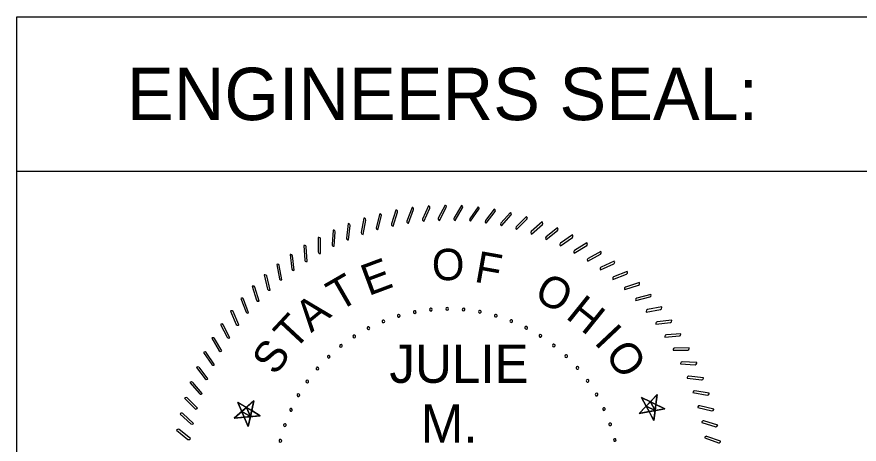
# Model space of a CAD drawing. Extents: x 0 to 34, y 0 to 22.
# Drawn here: x 9.25 to 11.982, y 5.614 to 7 of the extents above; entities that cross this region are included whole.
import ezdxf

# ---------------------------------------------------------------- set-up
doc = ezdxf.new("R2010")
doc.units = 0
doc.layers.add('Default', color=7, linetype='Continuous')
doc.layers.add('SH_Data', color=7, linetype='Continuous')

msp = doc.modelspace()

# ---------------------------------------------------------------- linework, layer by layer
at = {"layer": 'Default'}
for p, q in [((11.3269, 5.7755), (11.2684, 5.7141)), ((11.3519, 5.7294), (11.2753, 5.7661)), ((11.2753, 5.7661), (11.3157, 5.6914)), ((11.3157, 5.6914), (11.3269, 5.7755)), ((10.0187, 5.7548), (9.9551, 5.6985)), ((10.0396, 5.7067), (9.9665, 5.7497)), ((9.9665, 5.7497), (10.0003, 5.6719)), ((10.0003, 5.6719), (10.0187, 5.7548)), ((11.2907, 5.7375), (11.32, 5.7235)), ((11.32, 5.7235), (11.3046, 5.752)), ((9.9794, 5.72), (10.0073, 5.7036)), ((10.0073, 5.7036), (9.9944, 5.7333)), ((11.2684, 5.7141), (11.3519, 5.7294)), ((9.9551, 5.6985), (10.0396, 5.7067))]:
    msp.add_line(p, q, dxfattribs=at)
for points in [[(10.481, 6.373), (10.4791, 6.3736), (10.465, 6.3285)], [(10.4702, 6.3215), (10.4844, 6.3666)], [(10.5338, 6.3814), (10.532, 6.3821), (10.5152, 6.3379)], [(10.52, 6.3306), (10.5368, 6.3748)], [(10.587, 6.3866), (10.5852, 6.3874), (10.5658, 6.3443)], [(10.5702, 6.3367), (10.5896, 6.3798)], [(10.6404, 6.3886), (10.6387, 6.3895), (10.6168, 6.3476)], [(10.6206, 6.3399), (10.6426, 6.3817)], [(10.6939, 6.3874), (10.6922, 6.3884), (10.6678, 6.3479)], [(10.6712, 6.3399), (10.6956, 6.3804)], [(10.7472, 6.383), (10.7456, 6.3841), (10.7188, 6.3452)], [(10.7217, 6.337), (10.7485, 6.3759)], [(10.8001, 6.3754), (10.7985, 6.3766), (10.7695, 6.3394)], [(10.7719, 6.331), (10.801, 6.3683)], [(10.8525, 6.3647), (10.851, 6.366), (10.8197, 6.3305)], [(10.3774, 6.3469), (10.3754, 6.3472), (10.3668, 6.3008)], [(10.3728, 6.2945), (10.3815, 6.3409)], [(10.4288, 6.3615), (10.4269, 6.362), (10.4155, 6.3161)], [(10.4211, 6.3095), (10.4325, 6.3553)], [(10.5684, 6.3376), (10.5702, 6.3367)], [(10.6189, 6.3408), (10.6206, 6.3399)], [(10.6695, 6.3409), (10.6712, 6.3399)], [(10.7201, 6.3381), (10.7217, 6.337)], [(10.8217, 6.3221), (10.8529, 6.3575)], [(10.9041, 6.3509), (10.9027, 6.3523), (10.8694, 6.3187)], [(10.8708, 6.3102), (10.9041, 6.3437)], [(10.3269, 6.3292), (10.325, 6.3294), (10.3191, 6.2825)], [(10.3255, 6.2766), (10.3313, 6.3235)], [(10.4684, 6.3221), (10.4702, 6.3215)], [(10.5181, 6.3313), (10.52, 6.3306)], [(10.7704, 6.3322), (10.7719, 6.331)], [(10.8202, 6.3234), (10.8217, 6.3221)], [(10.8694, 6.3115), (10.8708, 6.3102)], [(10.9548, 6.334), (10.9535, 6.3354), (10.9183, 6.304)], [(10.9192, 6.2953), (10.9544, 6.3268)], [(11.0045, 6.3141), (11.0032, 6.3156), (10.9662, 6.2863)], [(10.2296, 6.285), (10.2277, 6.285), (10.2275, 6.2377)], [(10.2776, 6.3086), (10.2756, 6.3087), (10.2726, 6.2615)], [(10.2793, 6.256), (10.2824, 6.3032)], [(10.3709, 6.2948), (10.3728, 6.2945)], [(10.4192, 6.3099), (10.4211, 6.3095)], [(10.9179, 6.2968), (10.9192, 6.2953)], [(10.9666, 6.2776), (11.0036, 6.3069)], [(11.0128, 6.2571), (11.0515, 6.2842)], [(11.0528, 6.2913), (11.0517, 6.2929), (11.0129, 6.2658)], [(10.1831, 6.2586), (10.1812, 6.2585), (10.1838, 6.2113)], [(10.2345, 6.2326), (10.2347, 6.2799)], [(10.2774, 6.2561), (10.2793, 6.256)], [(10.3235, 6.2769), (10.3255, 6.2766)], [(10.9653, 6.2792), (10.9666, 6.2776)], [(11.0117, 6.2587), (11.0128, 6.2571)], [(11.0577, 6.2339), (11.098, 6.2586)], [(11.0997, 6.2656), (11.0987, 6.2673), (11.0583, 6.2426)], [(10.1383, 6.2295), (10.1363, 6.2293), (10.1418, 6.1823)], [(10.1911, 6.2066), (10.1885, 6.2538)], [(10.2325, 6.2326), (10.2345, 6.2326)], [(11.0567, 6.2356), (11.0577, 6.2339)], [(11.1012, 6.208), (11.1429, 6.2303)], [(11.145, 6.2371), (11.144, 6.2389), (11.1023, 6.2167)], [(10.1494, 6.1781), (10.1439, 6.225)], [(10.1892, 6.2065), (10.1911, 6.2066)], [(11.1002, 6.2098), (11.1012, 6.208)], [(11.1884, 6.206), (11.1876, 6.2078), (11.1447, 6.1881)], [(10.0953, 6.1977), (10.0933, 6.1974), (10.1016, 6.1509)], [(10.1094, 6.1471), (10.1012, 6.1936)], [(10.1474, 6.1779), (10.1494, 6.1781)], [(11.1422, 6.1814), (11.143, 6.1796)], [(11.143, 6.1796), (11.186, 6.1993)], [(11.23, 6.1724), (11.2293, 6.1742), (11.1852, 6.1572)], [(10.0542, 6.1635), (10.0523, 6.163), (10.0633, 6.117)], [(10.0714, 6.1138), (10.0604, 6.1597)], [(10.1075, 6.1467), (10.1094, 6.1471)], [(11.1823, 6.1506), (11.183, 6.1487)], [(11.183, 6.1487), (11.2271, 6.1658)], [(10.0153, 6.1268), (10.0135, 6.1262), (10.0272, 6.081)], [(10.0354, 6.0782), (10.0217, 6.1234)], [(11.2212, 6.1155), (11.2662, 6.1299)], [(11.2695, 6.1363), (11.2689, 6.1382), (11.2239, 6.1238)], [(10.0695, 6.1133), (10.0714, 6.1138)], [(11.2206, 6.1174), (11.2212, 6.1155)], [(11.2572, 6.0801), (11.303, 6.0918)], [(11.3067, 6.098), (11.3062, 6.0999), (11.2604, 6.0882)], [(9.9787, 6.0879), (9.9768, 6.0872), (9.9933, 6.0429)], [(10.0016, 6.0406), (9.9852, 6.0849)], [(10.0335, 6.0776), (10.0354, 6.0782)], [(11.2568, 6.082), (11.2572, 6.0801)], [(9.9444, 6.0468), (9.9426, 6.0461), (9.9617, 6.0028)], [(9.9702, 6.001), (9.9511, 6.0442)], [(9.9998, 6.0399), (10.0016, 6.0406)], [(11.2908, 6.0445), (11.2911, 6.0426)], [(11.2911, 6.0426), (11.3376, 6.0515)], [(11.3416, 6.0575), (11.3412, 6.0594), (11.2948, 6.0505)], [(11.374, 6.0149), (11.3737, 6.0169), (11.3269, 6.0107)], [(9.9127, 6.0038), (9.9109, 6.0029), (9.9325, 5.9609)], [(9.9411, 5.9596), (9.9195, 6.0016)], [(9.9684, 6.0002), (9.9702, 6.001)], [(11.3225, 6.005), (11.3227, 6.0031)], [(11.3227, 6.0031), (11.3696, 6.0092)], [(9.8836, 5.959), (9.8819, 5.958), (9.906, 5.9173)], [(9.9146, 5.9165), (9.8905, 5.9572)], [(9.9394, 5.9587), (9.9411, 5.9596)], [(11.3518, 5.9637), (11.3519, 5.9618)], [(11.3519, 5.9618), (11.3991, 5.9651)], [(11.4038, 5.9705), (11.4036, 5.9725), (11.3565, 5.9692)], [(9.8572, 5.9125), (9.8556, 5.9114), (9.882, 5.8722)], [(9.8907, 5.872), (9.8643, 5.9111)], [(9.9129, 5.9155), (9.9146, 5.9165)], [(11.3785, 5.9208), (11.3786, 5.9188)], [(11.3786, 5.9188), (11.4258, 5.9193)], [(11.4308, 5.9244), (11.4308, 5.9264), (11.3836, 5.9259)], [(11.4027, 5.8763), (11.4026, 5.8743)], [(11.4026, 5.8743), (11.4498, 5.872)], [(11.4551, 5.8768), (11.4552, 5.8788), (11.408, 5.8811)], [(9.8336, 5.8645), (9.8321, 5.8633), (9.8608, 5.8258)], [(9.8695, 5.826), (9.8408, 5.8636)], [(9.8891, 5.8709), (9.8907, 5.872)], [(9.868, 5.8248), (9.8695, 5.826)], [(11.4241, 5.8304), (11.4239, 5.8285)], [(11.4239, 5.8285), (11.4709, 5.8233)], [(11.4765, 5.8278), (11.4767, 5.8298), (11.4297, 5.8349)], [(9.813, 5.8152), (9.8115, 5.8139), (9.8425, 5.7782)], [(9.8511, 5.7789), (9.8202, 5.8147)], [(9.7954, 5.7647), (9.794, 5.7633), (9.827, 5.7295)], [(9.8356, 5.7308), (9.8025, 5.7646)], [(9.8496, 5.7777), (9.8511, 5.7789)], [(11.4428, 5.7833), (11.4425, 5.7814)], [(11.4425, 5.7814), (11.4891, 5.7735)], [(11.4949, 5.7776), (11.4952, 5.7796), (11.4487, 5.7875)], [(11.5103, 5.7264), (11.5107, 5.7283), (11.4647, 5.7391)], [(9.7808, 5.7133), (9.7794, 5.7118), (9.8144, 5.68)], [(9.8229, 5.6819), (9.7879, 5.7136)], [(9.8342, 5.7294), (9.8356, 5.7308)], [(11.4586, 5.7353), (11.4582, 5.7333)], [(11.4582, 5.7333), (11.5042, 5.7226)], [(9.8216, 5.6804), (9.8229, 5.6819)], [(11.4715, 5.6863), (11.471, 5.6844)], [(11.471, 5.6844), (11.5163, 5.671)], [(11.5226, 5.6744), (11.5232, 5.6763), (11.4778, 5.6897)], [(9.7693, 5.6611), (9.768, 5.6595), (9.8049, 5.6299)], [(9.8132, 5.6322), (9.7764, 5.6619)], [(9.812, 5.6307), (9.8132, 5.6322)], [(11.4815, 5.6367), (11.4808, 5.6348)], [(11.4808, 5.6348), (11.5252, 5.6187)], [(11.5318, 5.6217), (11.5324, 5.6236), (11.488, 5.6397)]]:
    msp.add_lwpolyline(points, dxfattribs=at)
for points in [[(11.2753, 5.7661), (11.3046, 5.752), (11.2753, 5.7661), (11.2907, 5.7375)], [(11.2907, 5.7375), (11.2753, 5.7661), (11.3046, 5.752), (11.3046, 5.752)], [(11.3269, 5.7755), (11.3046, 5.752), (11.3269, 5.7755), (11.3226, 5.7434)], [(11.3226, 5.7434), (11.3269, 5.7755), (11.3046, 5.752), (11.3046, 5.752)], [(9.9794, 5.72), (9.9665, 5.7497), (9.9944, 5.7333), (9.9944, 5.7333)], [(9.9665, 5.7497), (9.9944, 5.7333), (9.9665, 5.7497), (9.9794, 5.72)], [(10.0117, 5.7231), (10.0187, 5.7548), (9.9944, 5.7333), (9.9944, 5.7333)], [(10.0187, 5.7548), (9.9944, 5.7333), (10.0187, 5.7548), (10.0117, 5.7231)], [(11.2684, 5.7141), (11.2907, 5.7375), (11.2684, 5.7141), (11.3003, 5.7199)], [(11.3003, 5.7199), (11.2684, 5.7141), (11.2907, 5.7375), (11.2907, 5.7375)], [(11.2907, 5.7375), (11.32, 5.7235), (11.2907, 5.7375), (11.3046, 5.752)], [(11.3046, 5.752), (11.2907, 5.7375), (11.32, 5.7235), (11.32, 5.7235)], [(11.2907, 5.7375), (11.32, 5.7235), (11.2907, 5.7375), (11.3003, 5.7199)], [(11.3003, 5.7199), (11.2907, 5.7375), (11.32, 5.7235), (11.32, 5.7235)], [(11.32, 5.7235), (11.3226, 5.7434), (11.32, 5.7235), (11.3046, 5.752)], [(11.3046, 5.752), (11.32, 5.7235), (11.3226, 5.7434), (11.3226, 5.7434)], [(11.3226, 5.7434), (11.3519, 5.7294), (11.3226, 5.7434), (11.32, 5.7235)], [(11.32, 5.7235), (11.3226, 5.7434), (11.3519, 5.7294), (11.3519, 5.7294)], [(9.9874, 5.7016), (9.9551, 5.6985), (9.9794, 5.72), (9.9794, 5.72)], [(9.9551, 5.6985), (9.9794, 5.72), (9.9551, 5.6985), (9.9874, 5.7016)], [(9.9944, 5.7333), (9.9794, 5.72), (10.0073, 5.7036), (10.0073, 5.7036)], [(9.9794, 5.72), (10.0073, 5.7036), (9.9794, 5.72), (9.9944, 5.7333)], [(9.9874, 5.7016), (9.9794, 5.72), (10.0073, 5.7036), (10.0073, 5.7036)], [(9.9794, 5.72), (10.0073, 5.7036), (9.9794, 5.72), (9.9874, 5.7016)], [(9.9944, 5.7333), (10.0073, 5.7036), (10.0117, 5.7231), (10.0117, 5.7231)], [(10.0073, 5.7036), (10.0117, 5.7231), (10.0073, 5.7036), (9.9944, 5.7333)], [(10.0073, 5.7036), (10.0117, 5.7231), (10.0396, 5.7067), (10.0396, 5.7067)], [(10.0117, 5.7231), (10.0396, 5.7067), (10.0117, 5.7231), (10.0073, 5.7036)], [(11.32, 5.7235), (11.3157, 5.6914), (11.32, 5.7235), (11.3003, 5.7199)], [(11.3003, 5.7199), (11.32, 5.7235), (11.3157, 5.6914), (11.3157, 5.6914)], [(9.9874, 5.7016), (10.0073, 5.7036), (10.0003, 5.6719), (10.0003, 5.6719)], [(10.0073, 5.7036), (10.0003, 5.6719), (10.0073, 5.7036), (9.9874, 5.7016)]]:
    msp.add_lwpolyline(points, close=True, dxfattribs=at)
for centre, radius, start, end in [((10.4795, 6.3681), 0.00508, 342.6706, 72.6706), ((10.532, 6.3766), 0.00508, 339.242, 69.242), ((10.5849, 6.3819), 0.00508, 335.8134, 65.8134), ((10.6381, 6.3841), 0.00508, 332.3849, 62.3849), ((10.6913, 6.383), 0.00508, 328.9563, 58.9563), ((10.7443, 6.3788), 0.00508, 325.5277, 55.5277), ((10.797, 6.3714), 0.00508, 322.0992, 52.0992), ((10.8491, 6.3609), 0.00508, 318.6706, 48.6706), ((10.3765, 6.3419), 0.00508, 349.5277, 79.5277), ((10.4276, 6.3566), 0.00508, 346.0992, 76.0992), ((10.5199, 6.3361), 0.00508, 159.242, 249.242), ((10.5705, 6.3422), 0.00508, 155.8134, 245.8134), ((10.6213, 6.3453), 0.00508, 152.3849, 242.3849), ((10.6722, 6.3453), 0.00508, 148.9563, 238.9563), ((10.723, 6.3423), 0.00508, 145.5277, 235.5277), ((10.7735, 6.3362), 0.00508, 142.0992, 232.0992), ((10.9005, 6.3473), 0.00508, 315.242, 45.242), ((10.3263, 6.3242), 0.00508, 352.9563, 82.9563), ((10.4204, 6.3149), 0.00508, 166.0992, 256.0992), ((10.4699, 6.327), 0.00508, 162.6706, 252.6706), ((10.8236, 6.3272), 0.00508, 138.6706, 228.6706), ((10.873, 6.3152), 0.00508, 135.242, 225.242), ((10.951, 6.3306), 0.00508, 311.8134, 41.8134), ((11.0005, 6.3109), 0.00508, 308.3849, 38.3849), ((10.2296, 6.2799), 0.00508, 359.8134, 89.8134), ((10.2773, 6.3035), 0.00508, 356.3849, 86.3849), ((10.3718, 6.2998), 0.00508, 169.5277, 259.5277), ((10.9217, 6.3002), 0.00508, 131.8134, 221.8134), ((10.9693, 6.2823), 0.00508, 128.3849, 218.3849), ((11.0486, 6.2883), 0.00508, 304.9563, 34.9563), ((10.1834, 6.2535), 0.00508, 3.242, 93.242), ((10.2777, 6.2612), 0.00508, 176.3849, 266.3849), ((10.3242, 6.2819), 0.00508, 172.9563, 262.9563), ((11.0158, 6.2617), 0.00508, 124.9563, 214.9563), ((11.0954, 6.2629), 0.00508, 301.5277, 31.5277), ((10.1389, 6.2244), 0.00508, 6.6706, 96.6706), ((10.2325, 6.2377), 0.00508, 179.8134, 269.8134), ((11.061, 6.2382), 0.00508, 121.5277, 211.5277), ((11.1405, 6.2347), 0.00508, 298.0992, 28.0992), ((10.1889, 6.2116), 0.00508, 183.242, 273.242), ((11.1047, 6.2122), 0.00508, 118.0992, 208.0992), ((11.1838, 6.2039), 0.00508, 294.6706, 24.6706), ((10.0962, 6.1927), 0.00508, 10.0992, 100.0992), ((10.1468, 6.1829), 0.00508, 186.6706, 276.6706), ((11.1468, 6.1835), 0.00508, 114.6706, 204.6706), ((10.0554, 6.1585), 0.00508, 13.5277, 103.5277), ((10.1066, 6.1517), 0.00508, 190.0992, 280.0992), ((11.1871, 6.1524), 0.00508, 111.242, 201.242), ((11.2253, 6.1706), 0.00508, 291.242, 21.242), ((10.0168, 6.1219), 0.00508, 16.9563, 106.9563), ((11.2254, 6.119), 0.00508, 107.8134, 197.8134), ((11.2646, 6.1348), 0.00508, 287.8134, 17.8134), ((10.0683, 6.1182), 0.00508, 193.5277, 283.5277), ((11.3018, 6.0967), 0.00508, 284.3849, 14.3849), ((9.9805, 6.0831), 0.00508, 20.3849, 110.3849), ((10.0321, 6.0825), 0.00508, 196.9563, 286.9563), ((11.2617, 6.0833), 0.00508, 104.3849, 194.3849), ((9.9465, 6.0422), 0.00508, 23.8134, 113.8134), ((9.998, 6.0447), 0.00508, 200.3849, 290.3849), ((10.5403, 6.0428), 0.00437, 10.9091, 190.9091), ((10.5403, 6.0428), 0.00437, 190.9091, 10.9091), ((10.5929, 6.0505), 0.00437, 5.4545, 185.4545), ((10.5929, 6.0505), 0.00437, 185.4545, 5.4545), ((10.6459, 6.0531), 0.00437, 0, 180), ((10.6459, 6.0531), 0.00437, 180, 0), ((10.699, 6.0507), 0.00437, 354.5455, 174.5455), ((10.699, 6.0507), 0.00437, 174.5455, 354.5455), ((10.7516, 6.0433), 0.00437, 169.0909, 349.0909), ((10.7516, 6.0433), 0.00437, 349.0909, 169.0909), ((11.2958, 6.0455), 0.00508, 100.9563, 190.9563), ((11.3366, 6.0565), 0.00508, 280.9563, 10.9563), ((10.4386, 6.0127), 0.00437, 21.8182, 201.8182), ((10.4386, 6.0127), 0.00437, 201.8182, 21.8182), ((10.4887, 6.0302), 0.00437, 16.3636, 196.3636), ((10.4887, 6.0302), 0.00437, 196.3636, 16.3636), ((10.8032, 6.0309), 0.00437, 163.6364, 343.6364), ((10.8032, 6.0309), 0.00437, 343.6364, 163.6364), ((10.8534, 6.0137), 0.00437, 158.1818, 338.1818), ((10.8534, 6.0137), 0.00437, 338.1818, 158.1818), ((11.3275, 6.0057), 0.00508, 97.5277, 187.5277), ((11.3689, 6.0143), 0.00508, 277.5277, 7.5277), ((9.915, 5.9993), 0.00508, 27.242, 117.242), ((9.9663, 6.0048), 0.00508, 203.8134, 293.8134), ((10.3903, 5.9905), 0.00437, 27.2727, 207.2727), ((10.3903, 5.9905), 0.00437, 207.2727, 27.2727), ((10.9018, 5.9917), 0.00437, 152.7273, 332.7273), ((10.9018, 5.9917), 0.00437, 332.7273, 152.7273), ((9.8862, 5.9546), 0.00508, 30.6706, 120.6706), ((9.937, 5.9632), 0.00508, 207.242, 297.242), ((10.3444, 5.9638), 0.00437, 32.7273, 212.7273), ((10.3444, 5.9638), 0.00437, 212.7273, 32.7273), ((10.9479, 5.9653), 0.00437, 147.2727, 327.2727), ((10.9479, 5.9653), 0.00437, 327.2727, 147.2727), ((11.3568, 5.9641), 0.00508, 94.0992, 184.0992), ((11.3987, 5.9702), 0.00508, 274.0992, 4.0992), ((10.3012, 5.9329), 0.00437, 38.1818, 218.1818), ((10.3012, 5.9329), 0.00437, 218.1818, 38.1818), ((10.9912, 5.9346), 0.00437, 141.8182, 321.8182), ((10.9912, 5.9346), 0.00437, 321.8182, 141.8182), ((9.86, 5.9083), 0.00508, 34.0992, 124.0992), ((9.9103, 5.9199), 0.00508, 210.6706, 300.6706), ((10.2612, 5.8981), 0.00437, 43.6364, 223.6364), ((10.2612, 5.8981), 0.00437, 223.6364, 43.6364), ((11.0314, 5.8999), 0.00437, 136.3636, 316.3636), ((11.0314, 5.8999), 0.00437, 316.3636, 136.3636), ((11.3836, 5.9208), 0.00508, 90.6706, 180.6706), ((11.4258, 5.9244), 0.00508, 270.6706, 0.6706), ((11.4078, 5.876), 0.00508, 87.242, 177.242), ((11.45, 5.8771), 0.00508, 267.242, 357.242), ((9.8367, 5.8605), 0.00508, 37.5277, 127.5277), ((9.8862, 5.8751), 0.00508, 214.0992, 304.0992), ((10.2246, 5.8595), 0.00437, 49.0909, 229.0909), ((10.2246, 5.8595), 0.00437, 229.0909, 49.0909), ((11.0682, 5.8615), 0.00437, 130.9091, 310.9091), ((11.0682, 5.8615), 0.00437, 310.9091, 130.9091), ((9.8649, 5.8289), 0.00508, 217.5277, 307.5277), ((10.1919, 5.8177), 0.00437, 54.5455, 234.5455), ((10.1919, 5.8177), 0.00437, 234.5455, 54.5455), ((11.1011, 5.8198), 0.00437, 125.4545, 305.4545), ((11.1011, 5.8198), 0.00437, 305.4545, 125.4545), ((11.4292, 5.8299), 0.00508, 83.8134, 173.8134), ((11.4714, 5.8284), 0.00508, 263.8134, 353.8134), ((9.8163, 5.8113), 0.00508, 40.9563, 130.9563), ((9.7989, 5.7611), 0.00508, 44.3849, 134.3849), ((9.8463, 5.7815), 0.00508, 220.9563, 310.9563), ((10.1633, 5.773), 0.00437, 60, 240), ((10.1633, 5.773), 0.00437, 240, 60), ((11.1299, 5.7752), 0.00437, 120, 300), ((11.1299, 5.7752), 0.00437, 300, 120), ((11.4478, 5.7825), 0.00508, 80.3849, 170.3849), ((11.4899, 5.7785), 0.00508, 260.3849, 350.3849), ((11.4636, 5.7341), 0.00508, 76.9563, 166.9563), ((9.7845, 5.7099), 0.00508, 47.8134, 137.8134), ((9.8306, 5.7331), 0.00508, 224.3849, 314.3849), ((10.139, 5.7257), 0.00437, 65.4545, 245.4545), ((10.139, 5.7257), 0.00437, 245.4545, 65.4545), ((11.1543, 5.7281), 0.00437, 114.5455, 294.5455), ((11.1543, 5.7281), 0.00437, 294.5455, 114.5455), ((11.5053, 5.7276), 0.00508, 256.9563, 346.9563), ((11.1742, 5.6788), 0.00437, 109.0909, 289.0909), ((11.1742, 5.6788), 0.00437, 289.0909, 109.0909), ((11.4764, 5.6849), 0.00508, 73.5277, 163.5277), ((9.7732, 5.6579), 0.00508, 51.242, 141.242), ((9.8178, 5.6838), 0.00508, 227.8134, 317.8134), ((10.1194, 5.6763), 0.00437, 70.9091, 250.9091), ((10.1194, 5.6763), 0.00437, 250.9091, 70.9091), ((11.5177, 5.6758), 0.00508, 253.5277, 343.5277), ((9.808, 5.6339), 0.00508, 231.242, 321.242), ((10.1046, 5.6254), 0.00437, 76.3636, 256.3636), ((10.1046, 5.6254), 0.00437, 256.3636, 76.3636), ((11.1893, 5.6279), 0.00437, 103.6364, 283.6364), ((11.1893, 5.6279), 0.00437, 283.6364, 103.6364), ((11.4863, 5.6349), 0.00508, 70.0992, 160.0992), ((11.527, 5.6235), 0.00508, 250.0992, 340.0992)]:
    msp.add_arc(centre, radius, start, end, dxfattribs=at)
at = {"layer": 'SH_Data'}
for p, q in [((9.25, 3.75), (9.25, 7)), ((9.25, 7), (12.05, 7)), ((9.25, 6.5), (12.05, 6.5))]:
    msp.add_line(p, q, dxfattribs=at)

# ---------------------------------------------------------------- texts
at = {"layer": 'Default'}
for s, rotation, p in [('O', 0.9729, (10.5967, 6.1452)), ('F', 349.8625, (10.7305, 6.1414)), ('E', 20.4005, (10.3905, 6.0941)), ('T', 30.0029, (10.2939, 6.0427)), ('O', 331.5453, (10.9227, 6.0862)), ('H', 321.1241, (11.0266, 6.0253)), ('A', 39.086, (10.2046, 5.9741)), ('T', 47.0425, (10.1489, 5.9151)), ('I', 313.288, (11.1194, 5.9431)), ('S', 55.6603, (10.0901, 5.8335)), ('O', 305.5308, (11.154, 5.9055))]:
    msp.add_text(s, height=0.1017, rotation=rotation, dxfattribs=at).set_placement(p)
for s, p in [('JULIE', (10.4583, 5.8132)), ('M.', (10.5598, 5.6191))]:
    msp.add_text(s, height=0.12401, dxfattribs=at).set_placement(p)
at = {"layer": 'SH_Data'}
msp.add_text('ENGINEERS SEAL:', height=0.17, dxfattribs=at).set_placement((9.6074, 6.665))

doc.saveas('drawing.dxf')
